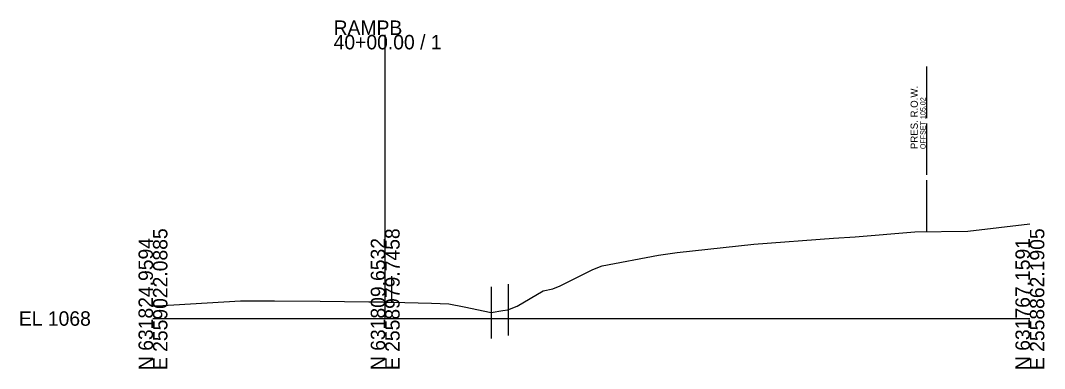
# Model space of a CAD drawing. Extents: x -985277 to -983967, y -985276 to -975706.
# Drawn here: x -985277.3 to -985078.8, y -985261.3 to -985193.9 of the extents above; entities that cross this region are included whole.
import ezdxf

# ---------------------------------------------------------------- set-up
doc = ezdxf.new("R2010")
doc.units = 0
for name, color, linetype in [('DESIGN - SCRATCH - User 1', 7, 'Continuous'), ('DESIGN - SCRATCH - User 2', 7, 'Continuous'), ('DESIGN - SHEET - Light Grid', 7, 'Continuous'), ('SURVEY - GROUND - Top of Ground', 7, 'Continuous'), ('SURVEY - PROPERTY - ROW Lines', 7, 'Continuous'), ('SURVEY - PROPERTY - ROW Lines Text', 7, 'Continuous')]:
    doc.layers.add(name, color=color, linetype=linetype)

msp = doc.modelspace()

# ---------------------------------------------------------------- linework, layer by layer
at = {"layer": 'DESIGN - SCRATCH - User 1'}
for p, q in [((-985182.8, -985244.95), (-985182.8, -985254.95)), ((-985186.06, -985245.48), (-985186.06, -985255.48))]:
    msp.add_line(p, q, dxfattribs=at)
at = {"layer": 'DESIGN - SCRATCH - User 2'}
msp.add_line((-985205.41, -985243.46), (-985205.41, -985248.46), dxfattribs=at)
at = {"layer": 'DESIGN - SHEET - Light Grid'}
for p, q in [((-985206.61, -985251.64), (-985206.61, -985196.67)), ((-985251.64, -985251.64), (-985206.61, -985251.64)), ((-985206.61, -985251.64), (-985081.61, -985251.64))]:
    msp.add_line(p, q, dxfattribs=at)
at = {"layer": 'SURVEY - GROUND - Top of Ground'}
msp.add_lwpolyline([(-985251.64, -985249.2), (-985250.84, -985249.16), (-985234.65, -985248.18), (-985231.95, -985248.18), (-985230.83, -985248.18), (-985228.06, -985248.2), (-985219.21, -985248.26), (-985209.76, -985248.39), (-985207.47, -985248.42), (-985207.1, -985248.43), (-985206.61, -985248.44), (-985205.41, -985248.46), (-985197.62, -985248.69), (-985194.29, -985248.78), (-985191.29, -985249.39), (-985186.08, -985250.48), (-985183.79, -985250.1), (-985182.86, -985249.97), (-985181.01, -985249.22), (-985175.96, -985246.27), (-985174.09, -985245.9), (-985172.69, -985245.31), (-985166.33, -985242.16), (-985164.53, -985241.42), (-985153.65, -985239.36), (-985149.98, -985238.85), (-985135.12, -985237.24), (-985119.68, -985236.07), (-985115.46, -985235.81), (-985103.9, -985234.84), (-985093.62, -985234.72), (-985081.61, -985233.31)], dxfattribs=at)
at = {"layer": 'SURVEY - PROPERTY - ROW Lines'}
for p, q in [((-985101.59, -985212.81), (-985101.59, -985202.81)), ((-985101.59, -985223.81), (-985101.59, -985213.81)), ((-985101.59, -985234.81), (-985101.59, -985224.81))]:
    msp.add_line(p, q, dxfattribs=at)

# ---------------------------------------------------------------- texts
at = {"layer": 'DESIGN - SHEET - Light Grid'}
for s, p in [('RAMPB', (-985216.61, -985196.67)), ('40+00.00 / 1', (-985216.61, -985199.47)), ('EL 1068', (-985277.64, -985253.04))]:
    msp.add_text(s, height=2.8, dxfattribs=at).set_placement(p)
for s, p in [('E 2559022.0885', (-985248.84, -985261.64)), ('E 2558979.7458', (-985203.81, -985261.64)), ('E 2558862.1905', (-985078.81, -985261.64)), ('N 631824.9594', (-985251.64, -985261.64)), ('N 631809.6532', (-985206.61, -985261.64)), ('N 631767.1591', (-985081.61, -985261.64))]:
    msp.add_text(s, height=2.8, rotation=90, dxfattribs=at).set_placement(p)
at = {"layer": 'SURVEY - PROPERTY - ROW Lines Text'}
for s, height, p in [('PRES. R.O.W.', 1.4, (-985103.34, -985218.81)), ('OFFSET 105.02', 1, (-985101.84, -985218.81))]:
    msp.add_text(s, height=height, rotation=90, dxfattribs=at).set_placement(p)

doc.saveas('drawing.dxf')
